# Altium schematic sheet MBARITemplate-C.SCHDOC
size C; Organization: Monterey Bay Aquarium Research Institute; Address1: 7700 Sandholdt Rd; Address2: Moss Landing, CA 95039-9644; CompanyName: MBARI
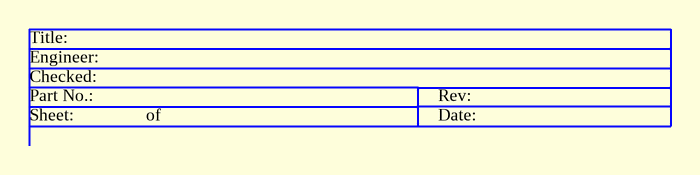
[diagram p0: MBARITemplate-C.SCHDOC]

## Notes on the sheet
- Title:
- Sheet:
- Engineer:
- Part No.:
- Checked:
- of
- Rev:
- Date:
